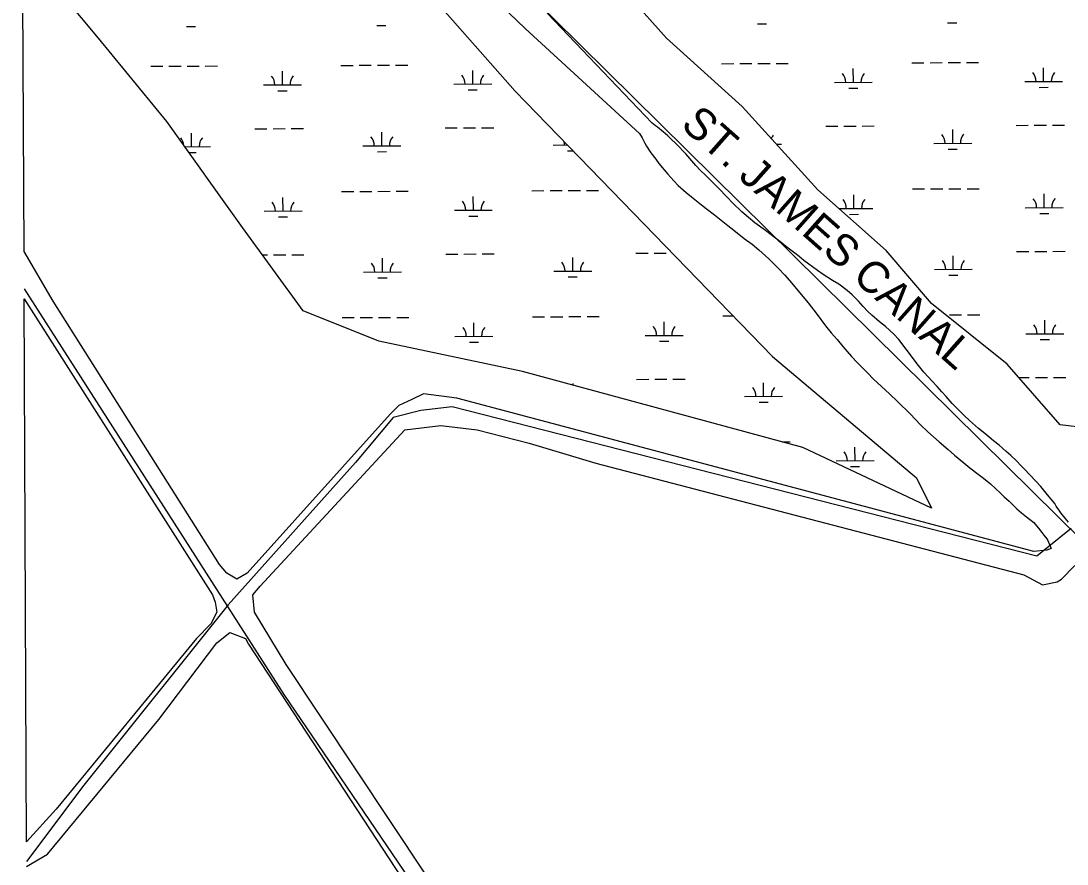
# Model space of a CAD drawing. Extents: x 3424494 to 3462436, y 522220 to 547718.
# Drawn here: x 3428603 to 3431362, y 528663 to 530887 of the extents above; entities that cross this region are included whole.
import ezdxf

# ---------------------------------------------------------------- set-up
doc = ezdxf.new("R2010")
doc.units = 0
for name, color, linetype in [('V-RIVR-IDEN', 7, 'Continuous'), ('V-SITE-VEGE', 7, 'Continuous'), ('V-TOPO-SHOR', 7, 'Continuous'), ('V-WETL-SWMP', 7, 'Continuous')]:
    doc.layers.add(name, color=color, linetype=linetype)

msp = doc.modelspace()

# ---------------------------------------------------------------- linework, layer by layer
at = {"layer": 'V-SITE-VEGE'}
for p, q in [((3428611, 530278.8), (3428603.3, 532176.3)), ((3429525.4, 531257.5), (3429933.2, 530866.4)), ((3430267.5, 530616.6), (3429991, 530907.2)), ((3429933.2, 530866.4), (3430234.6, 530589.8)), ((3430276.8, 530609.8), (3430267.5, 530616.6)), ((3430282.2, 530606), (3430276.8, 530609.8)), ((3430297.1, 530593.7), (3430282.2, 530606)), ((3430234.6, 530589.8), (3430241.5, 530578.3)), ((3430241.5, 530578.3), (3430248.4, 530564.5)), ((3430309.1, 530583.5), (3430297.1, 530593.7)), ((3430317.4, 530575.3), (3430309.1, 530583.5)), ((3430331.3, 530562), (3430317.4, 530575.3)), ((3430248.4, 530564.5), (3430253, 530556.7)), ((3430253, 530556.7), (3430264.5, 530538.7)), ((3430356.1, 530535.9), (3430331.3, 530562)), ((3430264.5, 530538.7), (3430277.4, 530521.8)), ((3430277.4, 530521.8), (3430285.3, 530510.9)), ((3430367.1, 530524), (3430356.1, 530535.9)), ((3430383.3, 530504.9), (3430367.1, 530524)), ((3430285.3, 530510.9), (3430299.2, 530493.6)), ((3430299.2, 530493.6), (3430309.1, 530482.1)), ((3430395.2, 530491.7), (3430383.3, 530504.9)), ((3430408.8, 530479.4), (3430395.2, 530491.7)), ((3430309.1, 530482.1), (3430325, 530464.7)), ((3430325, 530464.7), (3430336.6, 530452.8)), ((3430429, 530459.7), (3430408.8, 530479.4)), ((3430336.6, 530452.8), (3430357.2, 530434.4)), ((3430357.2, 530434.4), (3430371.1, 530422.8)), ((3430443, 530445.7), (3430429, 530459.7)), ((3430465.8, 530421.6), (3430443, 530445.7)), ((3430371.1, 530422.8), (3430402, 530398.2)), ((3430480.4, 530405.6), (3430465.8, 530421.6)), ((3430503.9, 530383.1), (3430480.4, 530405.6)), ((3430402, 530398.2), (3430410, 530391.8)), ((3430410, 530391.8), (3430432, 530375)), ((3430521.9, 530368.5), (3430503.9, 530383.1)), ((3430432, 530375), (3430449.9, 530361)), ((3430449.9, 530361), (3430467.2, 530347)), ((3430538.8, 530354.2), (3430521.9, 530368.5)), ((3430566.8, 530333.6), (3430538.8, 530354.2)), ((3430467.2, 530347), (3430483.5, 530334.7)), ((3430483.5, 530334.7), (3430510.7, 530313.2)), ((3430592.7, 530313.5), (3430566.8, 530333.6)), ((3430510.7, 530313.2), (3430531.7, 530297.8)), ((3430531.7, 530297.8), (3430549, 530282.8)), ((3430608.3, 530301.9), (3430592.7, 530313.5)), ((3430622.9, 530290.3), (3430608.3, 530301.9)), ((3428688.2, 530147.5), (3428611, 530278.8)), ((3430549, 530282.8), (3430575.5, 530259)), ((3430643.6, 530274.5), (3430622.9, 530290.3)), ((3430655.2, 530265.3), (3430643.6, 530274.5)), ((3430575.5, 530259), (3430600.7, 530234.1)), ((3430667.8, 530255.1), (3430655.2, 530265.3)), ((3430703.7, 530228.4), (3430667.8, 530255.1)), ((3430600.7, 530234.1), (3430617.3, 530215.8)), ((3430617.3, 530215.8), (3430634.8, 530196.1)), ((3430718.7, 530217.8), (3430703.7, 530228.4)), ((3430743.4, 530202.4), (3430718.7, 530217.8)), ((3430634.8, 530196.1), (3430660.9, 530165.5)), ((3430760.4, 530192.1), (3430743.4, 530202.4)), ((3430782.3, 530175.7), (3430760.4, 530192.1)), ((3430660.9, 530165.5), (3430679.5, 530143.4)), ((3430795.6, 530163.8), (3430782.3, 530175.7)), ((3430811.8, 530147.8), (3430795.6, 530163.8)), ((3428617.3, 528721.9), (3428611.5, 530153.6)), ((3428611.5, 530153.6), (3429107.9, 529372.7)), ((3429126.9, 529452.8), (3428688.2, 530147.5)), ((3430679.5, 530143.4), (3430702.6, 530112.2)), ((3430824.1, 530133.2), (3430811.8, 530147.8)), ((3430836.7, 530119.9), (3430824.1, 530133.2)), ((3430702.6, 530112.2), (3430725, 530082.4)), ((3430846.9, 530110.4), (3430836.7, 530119.9)), ((3430867.2, 530093), (3430846.9, 530110.4)), ((3430725, 530082.4), (3430739.9, 530064.1)), ((3430882.8, 530080.7), (3430867.2, 530093)), ((3430905.1, 530060.9), (3430882.8, 530080.7)), ((3430739.9, 530064.1), (3430755.4, 530046.4)), ((3430918.6, 530046), (3430905.1, 530060.9)), ((3430755.4, 530046.4), (3430771, 530028.1)), ((3430771, 530028.1), (3430793.8, 530001.6)), ((3430937.8, 530021.2), (3430918.6, 530046)), ((3430970.1, 529978.1), (3430937.8, 530021.2)), ((3430793.8, 530001.6), (3430809.7, 529984.9)), ((3430809.7, 529984.9), (3430835.6, 529958.4)), ((3430984.7, 529960.1), (3430970.1, 529978.1)), ((3430835.6, 529958.4), (3430851.8, 529942.1)), ((3430851.8, 529942.1), (3430893.3, 529903.2)), ((3431005.9, 529936.7), (3430984.7, 529960.1)), ((3431019.8, 529922.4), (3431005.9, 529936.7)), ((3431032, 529908.5), (3431019.8, 529922.4)), ((3429634.3, 529887.9), (3429600, 529872.7)), ((3429664.8, 529903.2), (3429634.3, 529887.9)), ((3429752.6, 529891.8), (3429664.8, 529903.2)), ((3431274.7, 529487.2), (3429752.6, 529891.8)), ((3430893.3, 529903.2), (3430915.2, 529882.5)), ((3430915.2, 529882.5), (3430948.7, 529849.1)), ((3431043.3, 529896.2), (3431032, 529908.5)), ((3431059.2, 529877.9), (3431043.3, 529896.2)), ((3429600, 529872.7), (3429577.1, 529849.8)), ((3431070.8, 529866), (3431059.2, 529877.9)), ((3431091, 529846.3), (3431070.8, 529866)), ((3429577.1, 529849.8), (3429199.4, 529429.9)), ((3430948.7, 529849.1), (3430974.5, 529822.6)), ((3431104.9, 529833), (3431091, 529846.3)), ((3431128.5, 529811.5), (3431104.9, 529833)), ((3430974.5, 529822.6), (3430995.1, 529802.8)), ((3430995.1, 529802.8), (3431009.7, 529789.6)), ((3431145.1, 529798.5), (3431128.5, 529811.5)), ((3431009.7, 529789.6), (3431024.6, 529776.6)), ((3431024.6, 529776.6), (3431048.5, 529756.1)), ((3431168, 529779.4), (3431145.1, 529798.5)), ((3431182.7, 529767.8), (3431168, 529779.4)), ((3431048.5, 529756.1), (3431065.5, 529741.8)), ((3431201.3, 529750.8), (3431182.7, 529767.8)), ((3431213.5, 529740.2), (3431201.3, 529750.8)), ((3431065.5, 529741.8), (3431089.4, 529721.4)), ((3431089.4, 529721.4), (3431106, 529708)), ((3431229.5, 529725.2), (3431213.5, 529740.2)), ((3431239.4, 529715), (3431229.5, 529725.2)), ((3431106, 529708), (3431127.9, 529691)), ((3431127.9, 529691), (3431141.6, 529681.1)), ((3431250, 529704.5), (3431239.4, 529715)), ((3431279.2, 529673.9), (3431250, 529704.5)), ((3431141.6, 529681.1), (3431159.9, 529666)), ((3431159.9, 529666), (3431186.7, 529640.8)), ((3431292.7, 529658.6), (3431279.2, 529673.9)), ((3431186.7, 529640.8), (3431196, 529631.7)), ((3431310.6, 529637.2), (3431292.7, 529658.6)), ((3431329.8, 529613.8), (3431310.6, 529637.2)), ((3431196, 529631.7), (3431209.3, 529619.7)), ((3431209.3, 529619.7), (3431229.9, 529600)), ((3431333.7, 529607), (3431329.8, 529613.8)), ((3431340, 529597.5), (3431333.7, 529607)), ((3431229.9, 529600), (3431241.5, 529589.4)), ((3431241.5, 529589.4), (3431255.1, 529578.8)), ((3431255.1, 529578.8), (3431262.8, 529573)), ((3431345.9, 529589.4), (3431340, 529597.5)), ((3431356.8, 529575.5), (3431345.9, 529589.4)), ((3431262.8, 529573), (3431274, 529563.5)), ((3431274, 529563.5), (3431281.3, 529555)), ((3431281.3, 529555), (3431286.6, 529548.5)), ((3431365.7, 529564.3), (3431356.8, 529575.5)), ((3431286.6, 529548.5), (3431295.2, 529537.3)), ((3431295.2, 529537.3), (3431301.1, 529530.2)), ((3431301.1, 529530.2), (3431308.7, 529520.7)), ((3431308.7, 529520.7), (3431311.7, 529516.6)), ((3431311.7, 529516.6), (3431320.4, 529494.8)), ((3431309, 529491), (3431274.7, 529487.2)), ((3431320.4, 529494.8), (3431309, 529491)), ((3429146, 529429.9), (3429126.9, 529452.8)), ((3429172.7, 529414.7), (3429146, 529429.9)), ((3429199.4, 529429.9), (3429172.7, 529414.7)), ((3429107.9, 529372.7), (3429115.5, 529353.6)), ((3429115.5, 529353.6), (3429119.3, 529326.9)), ((3429119.3, 529326.9), (3429104, 529296.3)), ((3429104, 529296.3), (3429065.9, 529258.2)), ((3429065.9, 529258.2), (3428695.9, 528807.8)), ((3429119.3, 529246.7), (3429153.6, 529273.4)), ((3429153.6, 529273.4), (3429195.6, 529258.2)), ((3429195.6, 529258.2), (3429203.2, 529242.9)), ((3428966.7, 529044.4), (3429119.3, 529246.7)), ((3429203.2, 529242.9), (3429683.9, 528510.1)), ((3428673, 528689.5), (3428966.7, 529044.4)), ((3428695.9, 528807.8), (3428617.3, 528721.9)), ((3428617.6, 528656.2), (3428673, 528689.5))]:
    msp.add_line(p, q, dxfattribs=at)
msp.add_lwpolyline([(3429947.1, 528220), (3429302.4, 529189.5), (3429218.5, 529326.9), (3429214.7, 529372.7), (3429233.7, 529395.6), (3429615.2, 529807.8), (3429710.6, 529819.2), (3429806, 529807.8), (3429943.3, 529773.4), (3430118.8, 529720), (3431248, 529426.1), (3431297.6, 529399.4), (3431335.7, 529407), (3431347.1, 529414.7), (3431382.8, 529450.8)], dxfattribs=at)
at = {"layer": 'V-TOPO-SHOR'}
for points in [[(3428602.8, 532280.9), (3431202.6, 529713.2), (3433228.4, 527712.9), (3433310.9, 527631.5)], [(3428611.4, 530180.3), (3429296.7, 529110.4), (3429957.3, 528138.1), (3430223.5, 527710.9), (3432443.2, 527627.6)], [(3431372.8, 529548.1), (3431282, 529474.8), (3429739.9, 529868.9), (3429657.9, 529859.4), (3429585, 529840.8), (3429485.3, 529721.9), (3429149.8, 529346.7), (3428769.1, 528871), (3428617.5, 528669.7)]]:
    msp.add_lwpolyline(points, dxfattribs=at)
at = {"layer": 'V-WETL-SWMP'}
for p, q in [((3429027.4, 531700.6), (3429906.2, 530701.2)), ((3430305.6, 530841.1), (3430145.8, 531021)), ((3428807.6, 530841.1), (3428707.8, 530961.1)), ((3430545.2, 530878.9), (3430569.2, 530879)), ((3431047.1, 530881.2), (3431071.1, 530881.3)), ((3429039.5, 530872.1), (3429063.5, 530872.2)), ((3429541.4, 530874.4), (3429565.4, 530874.5)), ((3428987.4, 530621.3), (3428807.6, 530841.1)), ((3430505.4, 530661.3), (3430305.6, 530841.1)), ((3428945.1, 530767), (3428977.1, 530767.2)), ((3428993.1, 530767.3), (3429025.1, 530767.4)), ((3429041.1, 530767.5), (3429073.1, 530767.6)), ((3429089.1, 530767.7), (3429121.1, 530767.8)), ((3429447, 530769.3), (3429479, 530769.4)), ((3429495, 530769.5), (3429527, 530769.7)), ((3429543, 530769.7), (3429575, 530769.9)), ((3429591, 530770), (3429623, 530770.1)), ((3430450.8, 530773.8), (3430482.8, 530774)), ((3430498.8, 530774), (3430530.8, 530774.2)), ((3430546.8, 530774.3), (3430578.8, 530774.4)), ((3430594.8, 530774.5), (3430626.8, 530774.6)), ((3430952.7, 530776.1), (3430984.7, 530776.2)), ((3431000.7, 530776.3), (3431032.7, 530776.5)), ((3431048.7, 530776.5), (3431080.7, 530776.7)), ((3431096.7, 530776.7), (3431128.7, 530776.9)), ((3429292.7, 530717.9), (3429292.5, 530753.9)), ((3429794.6, 530720.1), (3429794.4, 530756.1)), ((3430798.4, 530724.7), (3430798.2, 530760.7)), ((3431300.3, 530726.9), (3431300.1, 530762.9)), ((3429242.7, 530717.6), (3429342.7, 530718.1)), ((3429744.6, 530719.9), (3429844.6, 530720.4)), ((3430748.4, 530724.4), (3430848.4, 530724.9)), ((3430786.5, 530709.2), (3430810.5, 530709.3)), ((3431250.3, 530726.7), (3431350.3, 530727.1)), ((3431288.4, 530711.4), (3431312.4, 530711.5)), ((3429280.7, 530702.4), (3429304.7, 530702.5)), ((3429782.6, 530704.6), (3429806.6, 530704.7)), ((3429906.2, 530701.2), (3430585.3, 530001.7)), ((3430705.1, 530441.4), (3430505.4, 530661.3)), ((3429187.1, 530341.5), (3428987.4, 530621.3)), ((3429219.8, 530602.1), (3429251.8, 530602.2)), ((3429267.8, 530602.3), (3429299.8, 530602.5)), ((3429315.8, 530602.5), (3429347.8, 530602.7)), ((3429721.7, 530604.4), (3429753.7, 530604.5)), ((3429769.7, 530604.6), (3429801.7, 530604.7)), ((3429817.7, 530604.8), (3429849.7, 530604.9)), ((3430725.5, 530608.9), (3430757.5, 530609)), ((3430773.5, 530609.1), (3430805.5, 530609.3)), ((3430821.5, 530609.3), (3430853.5, 530609.5)), ((3431060.5, 530564), (3431060.4, 530600)), ((3431227.4, 530611.2), (3431259.4, 530611.3)), ((3431275.4, 530611.4), (3431307.4, 530611.5)), ((3431323.4, 530611.6), (3431355.4, 530611.7)), ((3429052.9, 530554.9), (3429052.8, 530590.9)), ((3429554.8, 530557.2), (3429554.7, 530593.2)), ((3429034.8, 530554.8), (3429102.9, 530555.1)), ((3429504.8, 530557), (3429604.8, 530557.4)), ((3430006.7, 530559.2), (3430043.9, 530559.4)), ((3430044.8, 530544), (3430058.8, 530544)), ((3430595.6, 530561.9), (3430608.6, 530561.9)), ((3431010.5, 530563.7), (3431110.5, 530564.2)), ((3431048.6, 530548.5), (3431072.6, 530548.6)), ((3429045.8, 530539.5), (3429065, 530539.5)), ((3429542.9, 530541.7), (3429566.9, 530541.8)), ((3429120.3, 530435.2), (3429122.6, 530435.2)), ((3429448.5, 530436.6), (3429480.5, 530436.8)), ((3429496.5, 530436.8), (3429528.5, 530437)), ((3429544.5, 530437.1), (3429576.5, 530437.2)), ((3429592.5, 530437.3), (3429624.5, 530437.4)), ((3429950.4, 530438.9), (3429982.4, 530439)), ((3429998.4, 530439.1), (3430030.4, 530439.3)), ((3430046.4, 530439.3), (3430078.4, 530439.5)), ((3430094.4, 530439.5), (3430126.4, 530439.7)), ((3430884.8, 530281.5), (3430705.1, 530441.4)), ((3430954.2, 530443.4), (3430986.2, 530443.6)), ((3431002.2, 530443.6), (3431034.2, 530443.8)), ((3431050.2, 530443.9), (3431082.2, 530444)), ((3431098.2, 530444.1), (3431130.2, 530444.2)), ((3429294.2, 530385.2), (3429294, 530421.2)), ((3429796.1, 530387.5), (3429795.9, 530423.5)), ((3430799.9, 530392), (3430799.7, 530428)), ((3431301.8, 530394.2), (3431301.6, 530430.2)), ((3429244.2, 530385), (3429344.2, 530385.4)), ((3429746.1, 530387.2), (3429846.1, 530387.7)), ((3430760.8, 530391.8), (3430849.9, 530392.2)), ((3431251.8, 530394), (3431351.8, 530394.5)), ((3431289.9, 530378.8), (3431313.9, 530378.9)), ((3429282.2, 530369.7), (3429306.2, 530369.8)), ((3429784.1, 530372), (3429808.1, 530372.1)), ((3430788, 530376.5), (3430812, 530376.6)), ((3429346.9, 530121.6), (3429187.1, 530341.5)), ((3429239.4, 530269.5), (3429253.3, 530269.6)), ((3429269.3, 530269.6), (3429301.3, 530269.8)), ((3429317.3, 530269.9), (3429349.3, 530270)), ((3429723.2, 530271.7), (3429755.2, 530271.8)), ((3429771.2, 530271.9), (3429803.2, 530272.1)), ((3429819.2, 530272.1), (3429851.2, 530272.3)), ((3430225.1, 530274), (3430257.1, 530274.1)), ((3430273.1, 530274.2), (3430305.1, 530274.3)), ((3431004.7, 530141.6), (3430884.8, 530281.5)), ((3431228.9, 530278.5), (3431260.9, 530278.6)), ((3431276.9, 530278.7), (3431308.9, 530278.8)), ((3431324.9, 530278.9), (3431356.9, 530279.1)), ((3429556.3, 530224.5), (3429556.2, 530260.5)), ((3430058.2, 530226.8), (3430058.1, 530262.8)), ((3431062, 530231.3), (3431061.9, 530267.3)), ((3429506.3, 530224.3), (3429606.3, 530224.7)), ((3430008.2, 530226.5), (3430108.2, 530227)), ((3431012, 530231.1), (3431112, 530231.5)), ((3431050.1, 530215.8), (3431074.1, 530215.9)), ((3429544.4, 530209), (3429568.4, 530209.1)), ((3430046.3, 530211.3), (3430070.3, 530211.4)), ((3431204.4, 529981.7), (3431004.7, 530141.6)), ((3429546.7, 530041.7), (3429346.9, 530121.6)), ((3429450, 530104), (3429482, 530104.1)), ((3429498, 530104.2), (3429530, 530104.3)), ((3429546, 530104.4), (3429578, 530104.5)), ((3429594, 530104.6), (3429626, 530104.8)), ((3429951.9, 530106.2), (3429983.9, 530106.4)), ((3429999.9, 530106.4), (3430031.9, 530106.6)), ((3430047.9, 530106.7), (3430079.9, 530106.8)), ((3430095.9, 530106.9), (3430127.9, 530107)), ((3430453.8, 530108.5), (3430481.5, 530108.6)), ((3431051.7, 530111.2), (3431083.7, 530111.3)), ((3431099.7, 530111.4), (3431131.7, 530111.5)), ((3429797.6, 530054.8), (3429797.4, 530090.8)), ((3430299.5, 530057), (3430299.3, 530093)), ((3431303.3, 530061.6), (3431303.1, 530097.6)), ((3429747.6, 530054.6), (3429847.6, 530055)), ((3430249.5, 530056.8), (3430349.5, 530057.3)), ((3431253.3, 530061.3), (3431353.3, 530061.8)), ((3429926.1, 529961.7), (3429546.7, 530041.7)), ((3429785.6, 530039.3), (3429809.6, 530039.4)), ((3430287.5, 530041.6), (3430311.5, 530041.7)), ((3431291.4, 530046.1), (3431315.4, 530046.2)), ((3430585.3, 530001.7), (3430964.7, 529681.9)), ((3431344.2, 529821.8), (3431204.4, 529981.7)), ((3430665.1, 529761.8), (3429926.1, 529961.7)), ((3430226.6, 529941.3), (3430258.6, 529941.4)), ((3430274.6, 529941.5), (3430306.6, 529941.6)), ((3430322.6, 529941.7), (3430354.6, 529941.9)), ((3431235.8, 529945.8), (3431262.4, 529946)), ((3431278.4, 529946), (3431310.4, 529946.2)), ((3431326.4, 529946.2), (3431358.4, 529946.4)), ((3430059.6, 529925.6), (3430059.6, 529930.1)), ((3430561.6, 529896.4), (3430561.5, 529932.4)), ((3430511.6, 529896.1), (3430611.6, 529896.6)), ((3430549.7, 529880.9), (3430573.7, 529881)), ((3431504, 529801.8), (3431344.2, 529821.8)), ((3430610.9, 529776.5), (3430631.3, 529776.6)), ((3431004.7, 529601.9), (3430665.1, 529761.8)), ((3430802.9, 529726.6), (3430802.7, 529762.6)), ((3430752.9, 529726.4), (3430852.9, 529726.9)), ((3430791, 529711.2), (3430815, 529711.3)), ((3430964.7, 529681.9), (3431004.7, 529601.9))]:
    msp.add_line(p, q, dxfattribs=at)
for centre, start, end in [((3429237.4, 530718.1), 359.4865, 41.0302), ((3429347.9, 530718.6), 139.4865, 181.0302), ((3429739.3, 530720.4), 359.4865, 41.0302), ((3429849.8, 530720.9), 139.4865, 181.0302), ((3430743.1, 530724.9), 359.4865, 41.0302), ((3430853.6, 530725.4), 139.4865, 181.0302), ((3431245, 530727.1), 359.4865, 41.0302), ((3431355.5, 530727.6), 139.4865, 181.0302), ((3428997.7, 530555.1), 4.0259, 41.0302), ((3429108.2, 530555.6), 139.4865, 181.0302), ((3429499.6, 530557.4), 359.4865, 41.0302), ((3429610.1, 530557.9), 139.4865, 181.0302), ((3430613.9, 530562.4), 139.4865, 155.4328), ((3431005.3, 530564.2), 359.4865, 41.0302), ((3431115.8, 530564.7), 139.4865, 181.0302), ((3430001.5, 530559.7), 359.4865, 13.1215), ((3429238.9, 530385.4), 359.4865, 41.0302), ((3429349.4, 530385.9), 139.4865, 181.0302), ((3429740.8, 530387.7), 359.4865, 41.0302), ((3429851.3, 530388.2), 139.4865, 181.0302), ((3430744.6, 530392.2), 359.4865, 41.0302), ((3430855.1, 530392.7), 139.4865, 181.0302), ((3431246.5, 530394.5), 359.4865, 41.0302), ((3431357, 530395), 139.4865, 181.0302), ((3429501.1, 530224.7), 359.4865, 41.0302), ((3429611.6, 530225.2), 139.4865, 181.0302), ((3430003, 530227), 359.4865, 41.0302), ((3430113.5, 530227.5), 139.4865, 181.0302), ((3431006.8, 530231.5), 359.4865, 41.0302), ((3431117.3, 530232), 139.4865, 181.0302), ((3429742.3, 530055), 359.4865, 41.0302), ((3429852.8, 530055.5), 139.4865, 181.0302), ((3430244.2, 530057.3), 359.4865, 41.0302), ((3430354.7, 530057.8), 139.4865, 181.0302), ((3431248, 530061.8), 359.4865, 41.0302), ((3431358.5, 530062.3), 139.4865, 181.0302), ((3430506.4, 529896.6), 359.4865, 41.0302), ((3430616.9, 529897.1), 139.4865, 181.0302), ((3430747.6, 529726.9), 359.4865, 41.0302), ((3430858.1, 529727.4), 139.4865, 181.0302)]:
    msp.add_arc(centre, 35.2, start, end, dxfattribs=at)

# ---------------------------------------------------------------- texts
at = {"layer": 'V-RIVR-IDEN'}
msp.add_text('ST. JAMES CANAL', height=83, rotation=318.4718, dxfattribs=at).set_placement((3430340, 530608.2))

doc.saveas('drawing.dxf')
